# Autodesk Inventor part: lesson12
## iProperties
Author: Administrator
Created: 2000-12
Part Number: lesson12
Document SubType Name: Modeling
Designer: Administrator
Control State: 0
Master: False
Checked Out: False
PropertySet Name: Design Tracking Control
Shininess: 0.0
PropertySet Name: _Private Model Information
Density: 0.0
Volumn: 0.0
Area: 0.0
PropertySet Name: Model Information
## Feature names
1. Extrusion1
2. Extrusion2
3. Hole1
4. Extrusion3
